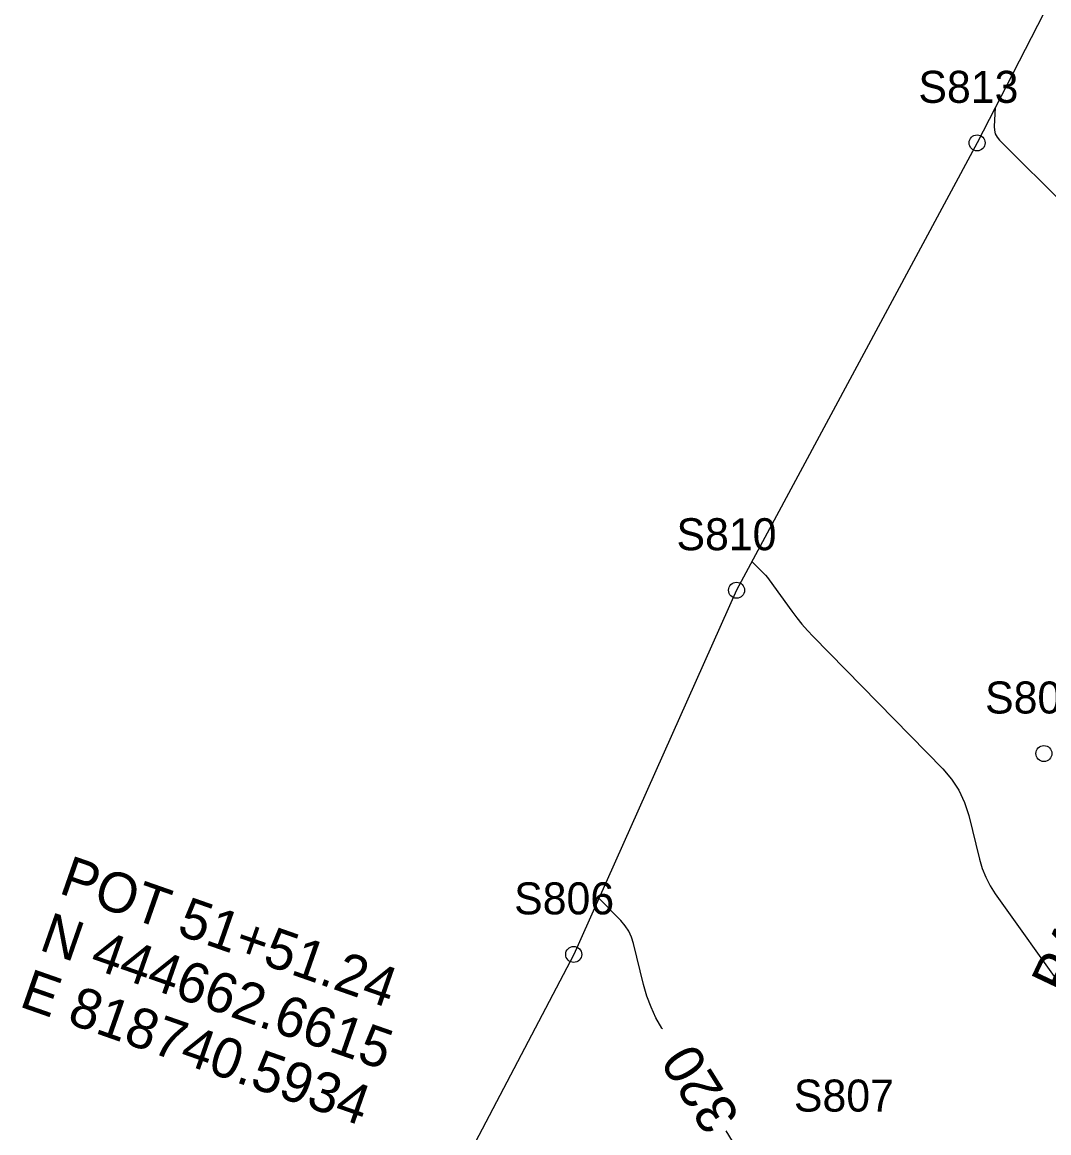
# Model space of a CAD drawing. Extents: x 816928 to 825690, y 436959 to 448212.
# Drawn here: x 818558.6 to 818686.8, y 444698.7 to 444837.4 of the extents above; entities that cross this region are included whole.
import ezdxf

# ---------------------------------------------------------------- set-up
doc = ezdxf.new("R2010")
doc.units = 0
for name, color, linetype in [('DESIGN - SCRATCH - User 1', 7, 'Continuous'), ('SURVEY - CENTERLINE - Preliminary Curve Text', 7, 'Continuous'), ('SURVEY - CONTOURS - Index with Text', 7, 'Continuous'), ('SURVEY - CONTOURS - Intermediate with optional Text', 7, 'Continuous'), ('SURVEY - DTM - Spot Points - Locators', 7, 'Continuous'), ('SURVEY - DTM - Spot Points - Point Numbers', 7, 'Continuous'), ('SURVEY - NON-TRANSPORTATION - Features Text', 7, 'Continuous')]:
    doc.layers.add(name, color=color, linetype=linetype)

msp = doc.modelspace()

# ---------------------------------------------------------------- linework, layer by layer
at = {"layer": 'DESIGN - SCRATCH - User 1'}
msp.add_lwpolyline([(818705.72, 444876.51), (818677.89, 444822.37), (818647.85, 444766.47), (818627.5, 444720.97), (818604.18, 444676.53), (818583.87, 444652.29), (818610.67, 444586.77), (818640.15, 444520.89), (818676.04, 444463.99)], dxfattribs=at)
at = {"layer": 'SURVEY - CONTOURS - Index with Text'}
for points in [[(818638.59, 444711.65), (818638.52, 444711.76), (818637.78, 444713.05), (818637.16, 444714.39), (818636.64, 444715.77), (818636.23, 444717.2), (818634.97, 444722.35), (818634.72, 444723.14), (818634.37, 444723.88), (818633.93, 444724.56), (818633.39, 444725.19), (818630.64, 444727.99)], [(818697.99, 444663.39), (818685.27, 444664.62), (818682.57, 444664.99), (818679.94, 444665.59), (818677.36, 444666.41), (818674.85, 444667.46), (818657.85, 444675.41), (818655.98, 444676.54), (818654.5, 444677.99), (818653.44, 444679.76), (818652.78, 444681.85), (818651.28, 444689.2), (818650.89, 444690.74), (818650.37, 444692.24), (818649.72, 444693.68), (818648.94, 444695.07), (818646.53, 444698.93)]]:
    msp.add_lwpolyline(points, dxfattribs=at)
at = {"layer": 'SURVEY - CONTOURS - Intermediate with optional Text'}
for points in [[(818680.15, 444826.77), (818680.03, 444824.43), (818680.05, 444823.95), (818680.16, 444823.5), (818680.38, 444823.09), (818680.68, 444822.72), (818689.15, 444814.28)], [(818649.77, 444770.05), (818650.98, 444768.87), (818651.23, 444768.61), (818651.47, 444768.34), (818651.7, 444768.07), (818651.91, 444767.78), (818654.74, 444763.85), (818655.36, 444763.02), (818656.01, 444762.22), (818656.69, 444761.44), (818657.41, 444760.69), (818673.6, 444744.17), (818674.71, 444742.88), (818675.62, 444741.48), (818676.34, 444739.97), (818676.85, 444738.34), (818678.19, 444732.86), (818678.53, 444731.71), (818678.97, 444730.6), (818679.52, 444729.55), (818680.17, 444728.54), (818688.78, 444716.46)]]:
    msp.add_lwpolyline(points, dxfattribs=at)
at = {"layer": 'SURVEY - DTM - Spot Points - Locators'}
for centre in [(818677.89, 444822.37), (818647.85, 444766.47), (818686.24, 444746.07), (818627.5, 444720.97)]:
    msp.add_circle(centre, 1, dxfattribs=at)

# ---------------------------------------------------------------- texts
at = {"layer": 'SURVEY - CENTERLINE - Preliminary Curve Text'}
for s, p in [('POT 51+51.24', (818563.04, 444728.67)), ('N 444662.6615', (818560.57, 444721.59)), ('E 818740.5934', (818558.09, 444714.51))]:
    msp.add_text(s, height=5, rotation=340.7277, dxfattribs=at).set_placement(p)
at = {"layer": 'SURVEY - CONTOURS - Index with Text'}
msp.add_text('320', height=5, rotation=121.9651, dxfattribs=at).set_placement((818648.36, 444700.72))
at = {"layer": 'SURVEY - DTM - Spot Points - Point Numbers'}
for s, p in [('S813', (818670.56, 444827.37)), ('S810', (818640.34, 444771.47)), ('S809', (818678.89, 444751.07)), ('S806', (818620.06, 444725.97)), ('S807', (818655.01, 444701.33))]:
    msp.add_text(s, height=4, dxfattribs=at).set_placement(p)
at = {"layer": 'SURVEY - NON-TRANSPORTATION - Features Text'}
msp.add_text('PASTURE', height=5, rotation=64.6538, dxfattribs=at).set_placement((818689.02, 444715.67))

doc.saveas('drawing.dxf')
